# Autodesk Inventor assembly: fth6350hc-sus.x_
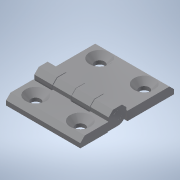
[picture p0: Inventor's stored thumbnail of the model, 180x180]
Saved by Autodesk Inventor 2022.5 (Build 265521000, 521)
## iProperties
Part Number: fth6350hc-sus.x_
Material: 一般
Document SubType Name: Assembly
Designer: ImaoCorp
Sending System: SOLIDWORKS 2017-2017317
MC: AMD64
MC_MODEL: Intel64 Family 6 Model 60 Stepping 3, GenuineIntel
OS: Windows_NT
FRU: Parasolid Version 29.0, build 201,  4-17-2017
FORMAT: text
GUISE: transmit
KEY: fth6350hc-sus
FILE: fth6350hc-sus.x_t
DATE: Mon May 13 14:28:23 2019
Author: ImaoCorp
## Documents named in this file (4)
- X:\14_SW2022-Inv2022\00_全2023-1023新製品(TCC)まで\f\fth6350hc-sus\FTH6350HC-SUS.iam
- X:\14_SW2022-Inv2022\00_全2023-1023新製品(TCC)まで\f\fth6350hc-sus\fth6350hc-sus_01.ipt
- X:\14_SW2022-Inv2022\00_全2023-1023新製品(TCC)まで\f\fth6350hc-sus\fth6350hc-sus_02.ipt
- X:\14_SW2022-Inv2022\00_全2023-1023新製品(TCC)まで\f\fth6350hc-sus\fth6350hc-sus_03.ipt
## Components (3 placed, 3 different names)
1. fth6350hc-sus_01
2. fth6350hc-sus_02
3. fth6350hc-sus_03
